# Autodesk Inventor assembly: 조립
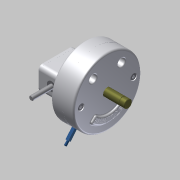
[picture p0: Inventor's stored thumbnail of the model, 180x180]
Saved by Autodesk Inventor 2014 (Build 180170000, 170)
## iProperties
Created: 2015-05
Part Number: 조립
Document SubType Name: Assembly
Designer: Administrator
Author: Administrator
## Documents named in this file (15)
- C:\Documents and Settings\Administrator\바탕 화면\350406V1018\조립.iam
- C:\Documents and Settings\Administrator\바탕 화면\350406V1018\본체.ipt
- C:\Documents and Settings\Administrator\바탕 화면\350406V1018\커버.ipt
- C:\Documents and Settings\Administrator\바탕 화면\350406V1018\M 10 x 35.ipt
- C:\Documents and Settings\Administrator\바탕 화면\350406V1018\축.ipt
- C:\Documents and Settings\Administrator\바탕 화면\350406V1018\멈춤링.ipt
- C:\Documents and Settings\Administrator\바탕 화면\350406V1018\베어링62_22.ipt
- C:\Documents and Settings\Administrator\바탕 화면\350406V1018\커버2.ipt
- C:\Documents and Settings\Administrator\바탕 화면\350406V1018\M 5 x 12.ipt
- C:\Documents and Settings\Administrator\바탕 화면\350406V1018\부시.ipt
- C:\Documents and Settings\Administrator\바탕 화면\350406V1018\스프링-[가변].ipt
- C:\Documents and Settings\Administrator\바탕 화면\350406V1018\슬라이더2.ipt
- C:\Documents and Settings\Administrator\바탕 화면\350406V1018\슬라이더.ipt
- C:\Documents and Settings\Administrator\바탕 화면\350406V1018\평행핀.ipt
- C:\Documents and Settings\Administrator\바탕 화면\350406V1018\슬라이더3.ipt
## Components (5 placed, 3 different names)
1. M 10 x 35:1
2. M 10 x 35:2
3. M 5 x 12:1
4. M 5 x 12:2
5. KS B 1320 B B 5 x  20:1 — 플러쉬:1
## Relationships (1: Flush 1)
- 플러쉬:1 [Flush]: KS B 1320 B B 5 x  20:1
